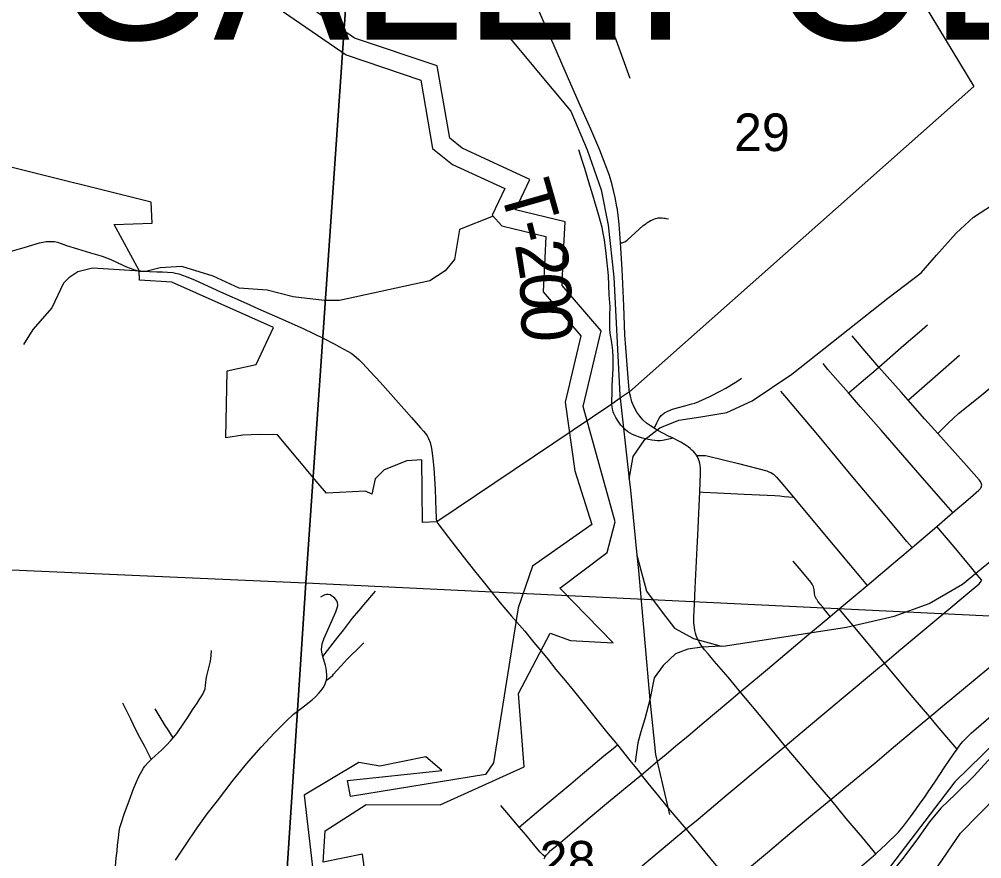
# Model space of a CAD drawing. Extents: x 0 to 34, y 0 to 22.
# Drawn here: x 28.376 to 29.449, y 19.659 to 20.594 of the extents above; entities that cross this region are included whole.
import ezdxf

# ---------------------------------------------------------------- set-up
doc = ezdxf.new("R2010")
doc.units = 0
for name, color, linetype in [('Default', 7, 'Continuous'), ('GM_X_City_Street', 7, 'Continuous'), ('GM_X_County_Road', 7, 'Continuous'), ('GM_X_Major_River', 7, 'Continuous'), ('GM_X_Minor_River', 7, 'Continuous'), ('GM_X_Rail_Line', 7, 'Continuous'), ('GM_X_Section', 7, 'Continuous'), ('GM_X_Section_Text', 7, 'Continuous'), ('GM_X_State_Route', 7, 'Continuous'), ('GM_X_Township_Road', 7, 'Continuous'), ('GM_X_Township_Road_Text', 7, 'Continuous'), ('GM_X_Township_Text', 7, 'Continuous'), ('SH_Text', 7, 'Continuous')]:
    doc.layers.add(name, color=color, linetype=linetype)

msp = doc.modelspace()

# ---------------------------------------------------------------- linework, layer by layer
at = {"layer": 'Default'}
for points in [[(28.7599, 20.9), (27.7187, 20.9), (27.6689, 20.0112), (28.6954, 19.9659)], [(29.8196, 20.9), (28.7599, 20.9), (28.6954, 19.9659), (29.6811, 19.9182), (29.6917, 19.9201), (29.703, 19.9232), (29.7227, 19.9266), (29.7379, 19.9286), (29.7546, 19.9305), (29.7719, 19.9386)]]:
    msp.add_lwpolyline(points, close=True, dxfattribs=at)
for points in [[(29.3843, 20.61), (29.4399, 20.5188), (29.056, 20.1786), (29.0473, 20.1728), (29.0362, 20.1651), (28.8413, 20.034), (28.8252, 20.033), (28.8245, 20.1031), (28.8079, 20.1018), (28.7826, 20.0917), (28.7724, 20.0818), (28.7688, 20.0648), (28.7618, 20.0682), (28.7183, 20.0659), (28.709, 20.0766), (28.6637, 20.1306), (28.6438, 20.1313), (28.6249, 20.1303), (28.6062, 20.1274), (28.6075, 20.2021), (28.6399, 20.209), (28.6592, 20.2502), (28.5458, 20.3008), (28.5098, 20.3031), (28.5096, 20.3138), (28.4815, 20.3652), (28.5239, 20.3667), (28.5231, 20.3898), (28.1905, 20.4727)], [(27.9525, 17.8831), (27.9847, 17.9912), (28.0266, 18.1245), (28.2096, 18.5267), (28.267, 18.6353), (28.332, 18.7085), (28.3661, 18.7612), (28.4364, 18.8208), (28.4791, 18.8705), (28.6246, 18.9977), (28.8094, 19.1502), (28.879, 19.2086), (29.0192, 19.305), (29.2694, 19.4948), (29.3261, 19.5426), (29.4248, 19.6871), (29.5488, 19.8131), (29.644, 19.878), (29.7344, 19.9057), (29.8761, 19.9228), (30.0125, 19.9577)], [(28.3661, 18.7612), (28.4364, 18.8208), (28.4791, 18.8705), (28.6246, 18.9977), (28.8094, 19.1502), (28.879, 19.2086), (29.0192, 19.305), (29.2694, 19.4948), (29.3261, 19.5426), (29.4248, 19.6871), (29.5488, 19.8131), (29.644, 19.878), (29.7344, 19.9057), (29.8761, 19.9228), (30.0125, 19.9577)]]:
    msp.add_lwpolyline(points, dxfattribs=at)
at = {"layer": 'GM_X_City_Street'}
for points in [[(29.3997, 20.1324), (29.4111, 20.1437), (29.4228, 20.1544), (29.4335, 20.1631), (29.4487, 20.1755), (29.4621, 20.1865), (29.4802, 20.2009), (29.4912, 20.2099), (29.5074, 20.2227), (29.5203, 20.2333), (29.5289, 20.2404), (29.556, 20.2631), (29.5651, 20.2703)], [(29.3001, 20.1774), (29.3039, 20.1806), (29.3144, 20.1894), (29.3309, 20.2035), (29.3341, 20.2063), (29.3618, 20.2305), (29.3792, 20.2455), (29.3881, 20.2534)], [(29.4486, 20.0747), (29.4484, 20.076), (29.4481, 20.0769), (29.4476, 20.0779), (29.4471, 20.0788), (29.4456, 20.0807), (29.4316, 20.0965), (29.3997, 20.1324), (29.3851, 20.1484), (29.3666, 20.1694), (29.3588, 20.1782), (29.3341, 20.2063), (29.3252, 20.2164), (29.3161, 20.2271), (29.3042, 20.2409)], [(29.3666, 20.1694), (29.3672, 20.1699), (29.3969, 20.1957), (29.4238, 20.2194)], [(29.4165, 20.0442), (29.4061, 20.0561), (29.3849, 20.0804), (29.3367, 20.1358), (29.3135, 20.1621), (29.3001, 20.1774), (29.2882, 20.1911), (29.2772, 20.2037), (29.2718, 20.2102)], [(29.0836, 20.1382), (29.0842, 20.1395), (29.0864, 20.1441), (29.088, 20.1471), (29.0894, 20.1498), (29.0913, 20.1524), (29.0931, 20.1539), (29.095, 20.1552), (29.0988, 20.1571), (29.1039, 20.1592), (29.1105, 20.1613), (29.1176, 20.1632), (29.1255, 20.1652), (29.129, 20.1662), (29.1333, 20.1679), (29.1376, 20.1697), (29.1456, 20.1735), (29.1577, 20.1799), (29.1635, 20.1829), (29.1738, 20.189), (29.1768, 20.1911), (29.1809, 20.1938)], [(29.371, 20.0053), (29.3652, 20.0121), (29.3524, 20.0272), (29.3314, 20.0525), (29.305, 20.0838), (29.2799, 20.1138), (29.2641, 20.1329), (29.2432, 20.1575), (29.2313, 20.1718), (29.2249, 20.1793)], [(29.1308, 20.1078), (29.1343, 20.1079), (29.1372, 20.1079), (29.1409, 20.1076), (29.1441, 20.1071), (29.1776, 20.0989), (29.209, 20.0906), (29.2114, 20.0897), (29.2135, 20.0887), (29.2164, 20.0868), (29.22, 20.0835), (29.2248, 20.0779), (29.2387, 20.0613), (29.242, 20.0574), (29.2715, 20.0221), (29.3134, 19.972), (29.3209, 19.9629)], [(28.9608, 19.6585), (28.962, 19.6608), (28.9631, 19.6624), (28.9643, 19.6638), (28.966, 19.6656), (28.9681, 19.6676), (28.9787, 19.6764), (28.9894, 19.6854), (29.0121, 19.7047), (29.035, 19.7238), (29.0618, 19.7459), (29.0694, 19.7521), (29.0874, 19.7672), (29.0969, 19.7752), (29.1077, 19.7842), (29.1214, 19.7956), (29.1394, 19.8108), (29.1666, 19.8336), (29.1795, 19.8444), (29.1813, 19.846), (29.2099, 19.8698), (29.2435, 19.8984), (29.2558, 19.9086), (29.2684, 19.919), (29.2798, 19.9285), (29.2896, 19.9368), (29.3209, 19.9629), (29.3552, 19.992), (29.371, 20.0053), (29.3986, 20.0287), (29.4165, 20.0442), (29.4362, 20.0611), (29.4454, 20.0692), (29.4471, 20.0709), (29.4477, 20.0717), (29.4483, 20.0727), (29.4485, 20.0737), (29.4486, 20.0747)], [(29.1345, 20.0672), (29.1383, 20.067), (29.1542, 20.0662), (29.1838, 20.0648), (29.2181, 20.0631), (29.2235, 20.0627), (29.2286, 20.0622), (29.2387, 20.0613)], [(29.4487, 19.9688), (29.4436, 19.975), (29.4377, 19.9823), (29.418, 20.006), (29.3986, 20.0287)], [(29.2798, 19.9285), (29.275, 19.9344), (29.2731, 19.9367), (29.2718, 19.9383), (29.2684, 19.9423), (29.2667, 19.9445), (29.2661, 19.9454), (29.2652, 19.9468), (29.2644, 19.9479), (29.263, 19.9507), (29.2626, 19.9522), (29.2622, 19.9536), (29.2621, 19.9555), (29.2619, 19.9573), (29.2618, 19.9586), (29.2614, 19.9601), (29.261, 19.9616), (29.2603, 19.963), (29.2597, 19.9644), (29.2582, 19.9665), (29.2568, 19.9684), (29.2452, 19.9821), (29.2384, 19.9901)], [(28.7141, 19.8839), (28.7311, 19.9054), (28.7371, 19.9133), (28.7474, 19.9265), (28.7543, 19.9348), (28.7622, 19.9439), (28.773, 19.9565)], [(28.5502, 19.6571), (28.561, 19.6736), (28.5741, 19.6929), (28.5854, 19.7086), (28.5967, 19.7229), (28.6131, 19.7446), (28.6292, 19.7643), (28.6456, 19.783), (28.6605, 19.7988), (28.6736, 19.8121), (28.6817, 19.8197), (28.6905, 19.8264), (28.7023, 19.8356), (28.7061, 19.839), (28.7099, 19.843), (28.7123, 19.846), (28.7145, 19.849), (28.716, 19.8515), (28.7169, 19.8533), (28.7177, 19.8555), (28.7182, 19.8576), (28.7186, 19.8605), (28.7187, 19.8632), (28.7184, 19.8673), (28.7178, 19.871), (28.7171, 19.8737), (28.7141, 19.8839), (28.7131, 19.8885), (28.7127, 19.8922), (28.713, 19.8947), (28.7136, 19.8979), (28.7158, 19.9044), (28.7217, 19.9176), (28.7286, 19.9336), (28.7303, 19.9382), (28.7308, 19.9407), (28.7308, 19.942), (28.7305, 19.9436), (28.7297, 19.9457), (28.7287, 19.9474), (28.7275, 19.9489), (28.7261, 19.9501), (28.724, 19.9515), (28.7223, 19.9524), (28.7203, 19.953), (28.7183, 19.953), (28.7163, 19.9526), (28.7142, 19.9516), (28.7116, 19.9501)], [(29.4211, 19.7806), (29.4099, 19.7939), (29.3971, 19.809), (29.3907, 19.8166), (29.3724, 19.8383), (29.3623, 19.8502), (29.3402, 19.8766), (29.3146, 19.9071), (29.3048, 19.9188), (29.2911, 19.9351), (29.2896, 19.9368)], [(28.4831, 19.65), (28.4839, 19.6595), (28.4849, 19.6672), (28.4855, 19.6738), (28.4864, 19.6813), (28.4873, 19.6892), (28.4881, 19.6935), (28.4893, 19.6978), (28.4932, 19.7095), (28.4983, 19.723), (28.5034, 19.7363), (28.5067, 19.7442), (28.5092, 19.75), (28.5127, 19.7567), (28.5144, 19.7595), (28.516, 19.7618), (28.52, 19.7663), (28.5231, 19.769), (28.5279, 19.7734), (28.5344, 19.7796), (28.5404, 19.7854), (28.5449, 19.7902), (28.5475, 19.7933), (28.5495, 19.7957), (28.5514, 19.7981), (28.5539, 19.8016), (28.557, 19.8061), (28.5594, 19.8097), (28.564, 19.8168), (28.5691, 19.8245), (28.5741, 19.8318), (28.5766, 19.8355), (28.5786, 19.8388), (28.5804, 19.8419), (28.5817, 19.8445), (28.583, 19.848), (28.5836, 19.8516), (28.584, 19.855), (28.5842, 19.8586), (28.5849, 19.8624), (28.589, 19.8786), (28.5896, 19.8818), (28.5898, 19.8849), (28.59, 19.8907)], [(28.7182, 19.8576), (28.7205, 19.8591), (28.7228, 19.8608), (28.7249, 19.8625), (28.7263, 19.8641), (28.73, 19.8682), (28.7345, 19.8733), (28.7414, 19.8808), (28.7569, 19.8961), (28.76, 19.899)], [(28.5231, 19.769), (28.522, 19.7711), (28.5194, 19.7763), (28.5157, 19.7835), (28.5101, 19.7936), (28.5055, 19.8028), (28.5001, 19.8139), (28.4953, 19.8238), (28.4912, 19.832)], [(28.5475, 19.7933), (28.5462, 19.7952), (28.5417, 19.8022), (28.5386, 19.8071), (28.5353, 19.8125), (28.5308, 19.8198), (28.5273, 19.8256)], [(28.9332, 19.6938), (28.9622, 19.7181), (28.9908, 19.7421), (29.0038, 19.7533), (29.0124, 19.7606), (29.0226, 19.7691), (29.0276, 19.7732), (29.0378, 19.7815), (29.0426, 19.7853)], [(29.2195, 19.5712), (29.1993, 19.5955), (29.1874, 19.6099), (29.1694, 19.6315), (29.1631, 19.639), (29.1508, 19.6537), (29.1403, 19.6664), (29.125, 19.6848), (29.1193, 19.6917), (29.1104, 19.7023), (29.0996, 19.715), (29.0886, 19.7283), (29.077, 19.7426), (29.0694, 19.7521)], [(28.962, 19.6608), (28.9595, 19.6629), (28.9578, 19.6645), (28.9564, 19.666), (28.9505, 19.6729), (28.9407, 19.6848), (28.9332, 19.6938), (28.9194, 19.7102), (28.9127, 19.718)], [(29.3307, 19.6641), (29.3277, 19.6677), (29.3158, 19.6822), (29.2977, 19.7035), (29.2803, 19.7244)]]:
    msp.add_lwpolyline(points, dxfattribs=at)
at = {"layer": 'GM_X_County_Road'}
for points in [[(29.0659, 19.6473), (29.0913, 19.6683), (29.1193, 19.6917), (29.1325, 19.7028), (29.1646, 19.7298), (29.2094, 19.7672), (29.2297, 19.7841), (29.2556, 19.8059), (29.2918, 19.8363), (29.3347, 19.8721), (29.3402, 19.8766), (29.3562, 19.89), (29.3987, 19.9254), (29.4437, 19.963), (29.4456, 19.9649), (29.4472, 19.9668), (29.4487, 19.9688)], [(29.3307, 19.6641), (29.3318, 19.665), (29.3418, 19.6744), (29.3559, 19.6882), (29.3616, 19.6947), (29.3694, 19.7051), (29.3752, 19.7133), (29.3801, 19.7203), (29.3848, 19.7269), (29.3891, 19.733), (29.3963, 19.7438), (29.4028, 19.7536), (29.4069, 19.7598), (29.4123, 19.768), (29.417, 19.7749), (29.4211, 19.7806), (29.4244, 19.785), (29.4277, 19.789), (29.4321, 19.7936), (29.437, 19.7983), (29.4423, 19.8032), (29.4813, 19.8369)], [(28.8879, 19.294), (28.903, 19.3065), (28.9245, 19.3244), (28.9425, 19.3395), (28.9503, 19.3464), (28.9576, 19.3529), (28.9658, 19.3595), (28.9796, 19.3703), (28.9988, 19.3864), (29.0316, 19.4132), (29.0602, 19.4373), (29.1092, 19.4784), (29.1189, 19.4865), (29.139, 19.5034), (29.1599, 19.521), (29.1871, 19.5437), (29.2094, 19.5626), (29.2195, 19.5712), (29.2245, 19.5755), (29.2613, 19.6061), (29.2856, 19.6264), (29.3176, 19.653), (29.3307, 19.6641)]]:
    msp.add_lwpolyline(points, dxfattribs=at)
at = {"layer": 'GM_X_Major_River'}
msp.add_lwpolyline([(29.7894, 19.9358), (29.7623, 19.9259), (29.6591, 19.9091), (29.6168, 19.8972), (29.5584, 19.865), (29.48, 19.804), (29.4186, 19.7441), (29.3363, 19.636)], dxfattribs=at)
at = {"layer": 'GM_X_Minor_River'}
for points in [[(28.5096, 20.9), (28.5182, 20.8959), (28.5168, 20.8613), (28.5074, 20.8487), (28.5785, 20.8106), (28.6551, 20.7069), (28.6444, 20.6203), (28.7402, 20.554), (28.8233, 20.5259), (28.8365, 20.4497), (28.8587, 20.4321), (28.9172, 20.4053), (28.9031, 20.3756), (28.9139, 20.3635), (28.9627, 20.3518), (28.9615, 20.3279), (28.9597, 20.2899), (29.0017, 20.241), (28.9843, 20.167)], [(29.0045, 20.1623), (29.0244, 20.2465), (28.9809, 20.2972), (28.9823, 20.3269), (28.9843, 20.368), (28.9289, 20.3813), (28.945, 20.4154), (28.8697, 20.45), (28.8557, 20.4611), (28.8418, 20.5417), (28.7497, 20.5728), (28.6666, 20.6303), (28.6768, 20.7126), (28.5925, 20.8268), (28.5374, 20.8563), (28.5392, 20.9)], [(28.9041, 20.3745), (28.8664, 20.3596), (28.8611, 20.3261), (28.8505, 20.3135), (28.8334, 20.3025), (28.7329, 20.2803), (28.7159, 20.2803), (28.681, 20.2845), (28.6522, 20.292), (28.6211, 20.2943), (28.5919, 20.3075), (28.5571, 20.3182), (28.5328, 20.317), (28.5169, 20.3128), (28.4574, 20.3165), (28.4411, 20.3123), (28.4312, 20.3058), (28.4252, 20.2998), (28.4123, 20.2724), (28.391, 20.248), (28.3808, 20.2313)], [(28.9843, 20.167), (28.9953, 20.0906), (29.014, 20.0308), (28.9481, 19.9843), (28.932, 19.9382), (28.9043, 19.7653), (28.8954, 19.7523), (28.745, 19.7278), (28.7417, 19.7456), (28.8467, 19.7568), (28.8291, 19.7722), (28.7776, 19.7615), (28.7544, 19.7658), (28.6934, 19.7292), (28.7045, 19.6333)], [(28.7647, 19.6168), (28.7584, 19.6638), (28.7148, 19.6547), (28.7167, 19.6896), (28.7626, 19.7189), (28.845, 19.7185), (28.9386, 19.7611), (28.9325, 19.8426), (28.9677, 19.9097), (28.9902, 19.9016), (29.0377, 19.8989), (28.9785, 19.9599), (29.0311, 19.9998), (29.0401, 20.0337), (29.0045, 20.1623)]]:
    msp.add_lwpolyline(points, dxfattribs=at)
at = {"layer": 'GM_X_Rail_Line'}
for points in [[(28.8375, 20.6688), (28.9217, 20.574), (28.9508, 20.5387), (28.9908, 20.4915), (29.0088, 20.4481), (29.0245, 20.4037), (29.0321, 20.3643), (29.0385, 20.3065), (29.0454, 20.1751), (29.0557, 20.0814), (29.057, 20.069), (29.0642, 19.9967), (29.0749, 19.9566), (29.0923, 19.9331), (29.1061, 19.9155), (29.1275, 19.9039), (29.1583, 19.8954), (29.1631, 19.8956), (29.1943, 19.9004), (29.2978, 19.9164), (29.3509, 19.9288), (29.39, 19.9429), (29.4273, 19.9643), (29.4647, 19.9954)], [(29.0557, 20.0814), (29.0601, 20.1066), (29.073, 20.1257), (29.0898, 20.1387), (29.1112, 20.1471), (29.1356, 20.1509), (29.1646, 20.1555), (29.1928, 20.1685), (29.2371, 20.1983), (29.3439, 20.283), (29.3813, 20.3112), (29.3981, 20.3311), (29.4202, 20.3555), (29.4393, 20.3731), (29.4744, 20.396), (29.5087, 20.4174), (29.5331, 20.4273), (29.5644, 20.4364), (29.5888, 20.4395), (29.6063, 20.4426), (29.6262, 20.4502)], [(29.0642, 19.9967), (29.0659, 19.9798), (29.0786, 19.8357)], [(29.1583, 19.8954), (29.1371, 19.8944), (29.1211, 19.8921), (29.1074, 19.8868), (29.0936, 19.8738), (29.0837, 19.8601), (29.0786, 19.8357)], [(29.0786, 19.8357), (29.073, 19.8143), (29.0685, 19.7998), (29.0654, 19.7876), (29.0624, 19.7662)], [(29.0786, 19.8357), (29.0849, 19.7747), (29.1007, 19.7078)]]:
    msp.add_lwpolyline(points, dxfattribs=at)
at = {"layer": 'GM_X_Section'}
msp.add_lwpolyline([(27.6689, 20.0112), (28.6954, 19.9659), (28.635, 19.0454), (28.6278, 19.0396), (28.6176, 19.0309), (28.6078, 19.0218), (28.5961, 19.0123), (28.5772, 18.9948), (28.5545, 18.9735), (28.5372, 18.9571), (28.5304, 18.9506), (28.5239, 18.9438), (27.6061, 18.9865)], close=True, dxfattribs=at)
msp.add_lwpolyline([(28.635, 19.0454), (28.6954, 19.9659), (29.6811, 19.9182), (29.6603, 19.9124), (29.6383, 19.904), (29.616, 19.8926), (29.6013, 19.883), (29.5601, 19.856), (29.5268, 19.8335), (29.5045, 19.8152), (29.4845, 19.7962), (29.463, 19.7757), (29.4403, 19.751), (29.4195, 19.7305), (29.4029, 19.7149), (29.3905, 19.6997), (29.3769, 19.6807), (29.3618, 19.6602), (29.3494, 19.645)], dxfattribs=at)
at = {"layer": 'GM_X_State_Route'}
for points in [[(29.0426, 20.3821), (29.0421, 20.3848), (29.04, 20.395), (29.0383, 20.403), (29.0368, 20.4092), (29.0337, 20.4195), (29.0291, 20.4324), (29.0229, 20.4479), (29.0128, 20.4714), (29.0014, 20.4968), (28.988, 20.5275), (28.9721, 20.564), (28.9559, 20.6017)], [(29.0562, 20.1781), (29.0557, 20.1811), (29.0544, 20.1944), (29.0519, 20.2282), (29.051, 20.242), (29.0496, 20.2745), (29.0478, 20.3155), (29.0462, 20.3445), (29.0446, 20.3655), (29.0434, 20.3756), (29.0427, 20.3812), (29.0426, 20.3821)], [(29.1436, 19.8869), (29.1398, 19.8914), (29.136, 19.8963), (29.1336, 19.9001), (29.1332, 19.9008), (29.1319, 19.9037), (29.1305, 19.9071), (29.1296, 19.91), (29.1289, 19.9127), (29.1284, 19.9162), (29.128, 19.9189), (29.1278, 19.9215), (29.1278, 19.9282), (29.1284, 19.942), (29.1293, 19.9603), (29.1316, 20.005), (29.1322, 20.0191), (29.1342, 20.0595), (29.1345, 20.0672), (29.1353, 20.0878), (29.1352, 20.0931), (29.1349, 20.0971), (29.1341, 20.1008), (29.133, 20.1038), (29.1317, 20.1064), (29.1308, 20.1078), (29.1302, 20.1087), (29.1276, 20.1117), (29.1257, 20.1136), (29.1236, 20.1156), (29.1214, 20.1174), (29.1193, 20.1189), (29.1131, 20.1225), (29.1089, 20.1247), (29.1047, 20.1269), (29.104, 20.1273), (29.0995, 20.1294), (29.0869, 20.1361), (29.0836, 20.1382), (29.0796, 20.1407), (29.0751, 20.1439), (29.071, 20.1476), (29.0674, 20.1516), (29.0642, 20.1561), (29.0613, 20.1615), (29.0588, 20.1677), (29.0578, 20.1708), (29.0571, 20.1737), (29.0562, 20.1781)], [(29.2803, 19.7244), (29.2959, 19.7374), (29.3295, 19.7652), (29.3502, 19.7828), (29.3779, 19.8059), (29.3907, 19.8166), (29.4068, 19.83), (29.426, 19.8461), (29.4564, 19.8714), (29.4744, 19.8866), (29.487, 19.897), (29.4998, 19.9074)], [(29.2803, 19.7244), (29.2639, 19.7437), (29.2297, 19.7841), (29.2184, 19.7976), (29.1971, 19.8232), (29.1795, 19.8444), (29.1659, 19.8608), (29.1504, 19.8787), (29.1455, 19.8846), (29.1436, 19.8869)], [(29.003, 19.4918), (29.0068, 19.495), (29.0389, 19.5219), (29.059, 19.5388), (29.0679, 19.5462), (29.1128, 19.584), (29.1344, 19.6023), (29.1647, 19.6275), (29.1694, 19.6315), (29.1788, 19.6394), (29.2098, 19.6655), (29.2349, 19.6865), (29.2601, 19.7077), (29.2803, 19.7244)]]:
    msp.add_lwpolyline(points, dxfattribs=at)
at = {"layer": 'GM_X_Township_Road'}
for points in [[(28.9379, 20.6352), (28.9646, 20.6278), (28.9826, 20.6399), (28.9915, 20.6453), (28.9985, 20.649), (29.0032, 20.6513), (29.0072, 20.6457), (29.0093, 20.6424), (29.0179, 20.6277), (29.0225, 20.6192), (29.025, 20.6138), (29.0287, 20.6049), (29.0564, 20.5281)], [(29.0364, 20.1646), (29.0365, 20.1704), (29.0366, 20.1754), (29.0369, 20.1859), (29.0377, 20.2046), (29.0379, 20.2106), (29.0377, 20.2171), (29.0373, 20.2247), (29.0362, 20.2335), (29.0346, 20.2442), (29.0342, 20.2487), (29.0341, 20.2538), (29.0343, 20.2637), (29.0344, 20.2732), (29.0335, 20.2868), (29.0325, 20.3084), (29.0299, 20.3326), (29.0281, 20.348), (29.0268, 20.3555), (29.0256, 20.3616), (29.022, 20.3752), (29.0151, 20.3979), (29.0108, 20.4121), (29.0063, 20.4273), (29.0038, 20.4353), (28.9995, 20.4481)], [(29.0462, 20.3445), (29.0477, 20.3447), (29.0487, 20.3449), (29.0497, 20.3453), (29.0508, 20.3458), (29.0533, 20.3477), (29.0712, 20.3638), (29.0741, 20.366), (29.0755, 20.3671), (29.0766, 20.3678), (29.0781, 20.3686), (29.0796, 20.3694), (29.0811, 20.3701), (29.0831, 20.3711), (29.0851, 20.3718), (29.0868, 20.3723), (29.0879, 20.3725), (29.0894, 20.3726), (29.0921, 20.3725), (29.0944, 20.3723), (29.0953, 20.3722), (29.0967, 20.3719), (29.0994, 20.3714)], [(28.3632, 20.3341), (28.3814, 20.3395), (28.3985, 20.3446), (28.4022, 20.3454), (28.4058, 20.346), (28.4101, 20.3463), (28.415, 20.346), (28.4186, 20.3453), (28.4227, 20.3439), (28.4285, 20.3418), (28.4409, 20.3379), (28.4553, 20.3334), (28.4683, 20.3297), (28.4778, 20.3262), (28.4912, 20.3198), (28.4954, 20.3179), (28.4994, 20.3164), (28.5045, 20.3146), (28.5098, 20.3132), (28.5107, 20.3132)], [(28.5107, 20.3132), (28.5212, 20.3127), (28.5292, 20.3125), (28.5357, 20.3122), (28.5413, 20.312), (28.547, 20.3115), (28.5502, 20.311), (28.5537, 20.3102), (28.5621, 20.3073), (28.572, 20.3031), (28.6003, 20.2901), (28.6287, 20.2773), (28.6425, 20.2712), (28.6664, 20.2607)], [(28.6664, 20.2607), (28.6925, 20.2493), (28.7154, 20.238), (28.7268, 20.232), (28.7328, 20.2289), (28.737, 20.2267), (28.7424, 20.2238), (28.746, 20.2216), (28.7489, 20.2195), (28.7519, 20.2171), (28.7546, 20.2145), (28.7584, 20.2107), (28.7675, 20.2009), (28.778, 20.1895), (28.8074, 20.1565), (28.813, 20.15), (28.8232, 20.1386), (28.8266, 20.1347), (28.8287, 20.1322), (28.8305, 20.1297), (28.8321, 20.1266), (28.8339, 20.1221), (28.8351, 20.1174), (28.8358, 20.1133), (28.8369, 20.1041), (28.8379, 20.0935), (28.8395, 20.0701), (28.8399, 20.0583), (28.8403, 20.046), (28.8405, 20.039), (28.8407, 20.0366), (28.8415, 20.0335)], [(29.1047, 20.1269), (29.1016, 20.1262), (29.0948, 20.1248), (29.0927, 20.1244), (29.0901, 20.1242), (29.0873, 20.1242), (29.0844, 20.1244), (29.0809, 20.1248), (29.0772, 20.1255), (29.0706, 20.1272), (29.0662, 20.1286), (29.0625, 20.13), (29.0594, 20.1313), (29.0569, 20.1326), (29.0541, 20.1343), (29.0513, 20.1367), (29.0489, 20.1389), (29.0464, 20.1417), (29.0433, 20.1459), (29.0409, 20.15), (29.0386, 20.1546), (29.038, 20.1565), (29.0372, 20.1593), (29.0366, 20.1622), (29.0364, 20.1646)], [(28.8415, 20.0335), (28.8425, 20.032), (28.8472, 20.0256), (28.8545, 20.0163), (28.8608, 20.0081), (28.8708, 19.9954), (28.8779, 19.9863), (28.8834, 19.9794), (28.8929, 19.9674), (28.9118, 19.9437), (28.9246, 19.9289), (28.9393, 19.912), (28.9496, 19.8995), (28.9584, 19.889), (28.9653, 19.8804), (28.974, 19.8695), (28.9846, 19.8567), (28.9932, 19.8464), (29.0027, 19.8347), (29.0304, 19.7999), (29.0426, 19.7853), (29.0566, 19.7681), (29.0653, 19.7571), (29.0694, 19.7521)]]:
    msp.add_lwpolyline(points, dxfattribs=at)
at = {"layer": 'SH_Text'}
msp.add_lwpolyline([(27.9525, 17.8831), (27.9847, 17.9912), (28.0266, 18.1245), (28.2096, 18.5267), (28.267, 18.6353), (28.332, 18.7085), (28.3661, 18.7612), (28.4364, 18.8208), (28.4791, 18.8705), (28.6246, 18.9977), (28.8094, 19.1502), (28.879, 19.2086), (29.0192, 19.305), (29.2694, 19.4948), (29.3261, 19.5426), (29.4248, 19.6871), (29.5488, 19.8131), (29.644, 19.878), (29.7344, 19.9057), (29.8761, 19.9228), (30.0125, 19.9577)], dxfattribs=at)

# ---------------------------------------------------------------- texts
at = {"layer": 'GM_X_Section_Text'}
for s, p in [('29', (29.1725, 20.4469)), ('28', (28.9558, 19.6365))]:
    msp.add_text(s, height=0.04186, rotation=0, dxfattribs=at).set_placement(p)
at = {"layer": 'GM_X_Township_Road_Text'}
for s, rotation, p in [('T', 285.9148, (28.911, 20.4049)), ('-', 284.4281, (28.9226, 20.3645)), ('2', 279.0405, (28.9281, 20.3432)), ('0', 272.629, (28.9334, 20.3103)), ('0', 271.6238, (28.935, 20.2756))]:
    msp.add_text(s, height=0.0568, rotation=rotation, dxfattribs=at).set_placement(p)
at = {"layer": 'GM_X_Township_Text'}
msp.add_text('GALLIPOLIS', height=0.17045, rotation=0, dxfattribs=at).set_placement((28.415, 20.571))

doc.saveas('drawing.dxf')
